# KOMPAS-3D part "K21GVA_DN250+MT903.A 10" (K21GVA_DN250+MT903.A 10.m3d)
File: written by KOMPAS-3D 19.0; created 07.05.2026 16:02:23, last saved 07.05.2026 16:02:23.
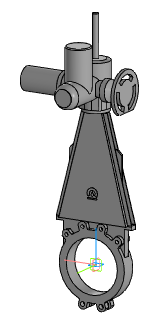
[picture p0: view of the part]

Document properties: Автор: Энергия; Полное имя файла: ..\K21GVA_DN50-DN1000+MT903.A\K21GVA_DN250+MT903.A 10.a3d

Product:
- Part/product: K21GVA_DN250+MT903.A 10
    Масса: 116.16

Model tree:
1. Операция без истории:1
